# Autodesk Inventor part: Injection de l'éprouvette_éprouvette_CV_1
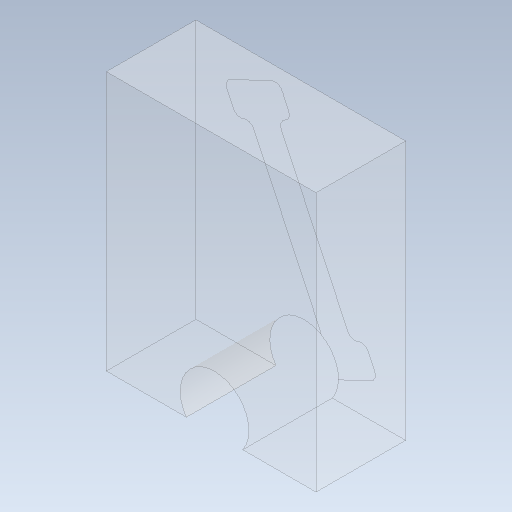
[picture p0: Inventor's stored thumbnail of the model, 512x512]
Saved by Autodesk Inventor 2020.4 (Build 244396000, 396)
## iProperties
Created: 2021-10
Part Number: Injection de l'éprouvette_éprouvette_CV_1
Material: Générique
Document SubType Name: Modeling
Designer: mel
Density: 1 g/cm^3
Appearance: Par défaut
Author: mel
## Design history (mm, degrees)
node "Injection de l'éprouvette_éprouvette_CV_Base"
feature "Sculpter3"
feature "Solide2::Injection de l'éprouvette_éprouvette_CV_Base"
tag "FonctionRepérage2"
node "Solide2"
feature "Injection de l'éprouvette_éprouvette_CV_Base_Corps"
feature "Surface3"
body "Srf3"
